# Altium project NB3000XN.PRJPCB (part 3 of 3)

## Sheet LED_RGB_SMDx8.SCHDOC: Visual Indicators
size A4; DocumentNumber: 10; SheetNumber: 11; SheetTotal: 78
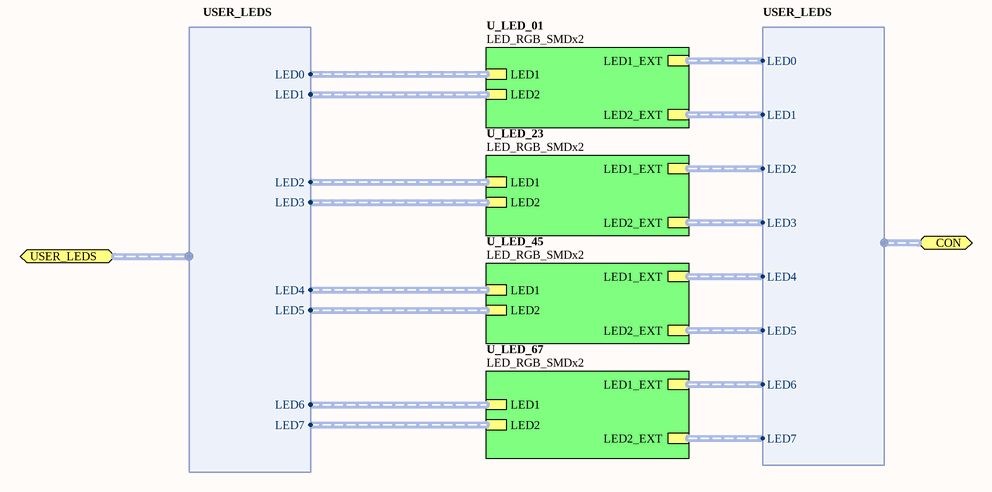
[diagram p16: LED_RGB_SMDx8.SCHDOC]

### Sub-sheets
U_LED_01 = LED_RGB_SMDx2 (file not in this document): LED1 (harness RGB_LED), LED2 (harness RGB_LED), LED1_EXT (harness RGB_LED), LED2_EXT (harness RGB_LED)
U_LED_23 = LED_RGB_SMDx2 (file not in this document): LED1 (harness RGB_LED), LED2 (harness RGB_LED), LED1_EXT (harness RGB_LED), LED2_EXT (harness RGB_LED)
U_LED_45 = LED_RGB_SMDx2 (file not in this document): LED1 (harness RGB_LED), LED2 (harness RGB_LED), LED1_EXT (harness RGB_LED), LED2_EXT (harness RGB_LED)
U_LED_67 = LED_RGB_SMDx2 (file not in this document): LED1 (harness RGB_LED), LED2 (harness RGB_LED), LED1_EXT (harness RGB_LED), LED2_EXT (harness RGB_LED)

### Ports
CON (harness USER_LEDS), USER_LEDS (harness USER_LEDS)

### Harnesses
USER_LEDS: LED0, LED1, LED2, LED3, LED4, LED5, LED6, LED7

## Sheet Audio_Codec.SchDoc: Audio CODEC
size A4; DocumentNumber: 4; SheetNumber: 6; SheetTotal: 78
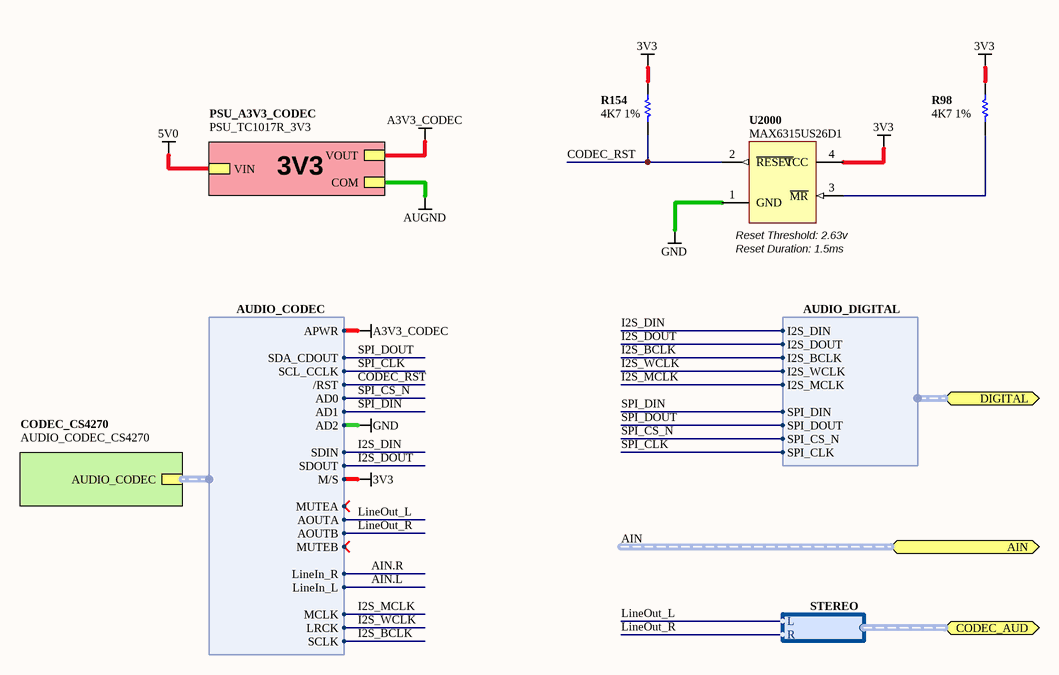
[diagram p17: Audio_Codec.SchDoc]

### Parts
(Parts that share a designator on the sheet are numbered #1, #2 ... from top to bottom, then left to right.)
R98  4K7 1%  [RESC1005-STAR]
R154#2  4K7 1%  [RESC1005-STAR]
U2000  MAX6315US26D1  [SOT143]

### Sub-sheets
CODEC_CS4270 = AUDIO_CODEC_CS4270 (file not in this document): AUDIO_CODEC (harness AUDIO_CODEC)
PSU_A3V3_CODEC = PSU_TC1017R_3V3 (file not in this document): VIN, VOUT, COM

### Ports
AIN (harness AUDIO_IN), CODEC_AUD (harness STEREO), DIGITAL (harness AUDIO_DIGITAL)

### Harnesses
AUDIO_CODEC: SDOUT, SDIN, SCLK, LRCK, MCLK, M/S, LineIn_L, LineIn_R, AOUTA, AOUTB, APWR, SCL_CCLK, AD1, SDA_CDOUT, AD0, AD2, /RST, MUTEA, MUTEB
AUDIO_DIGITAL: I2S_DOUT, I2S_DIN, I2S_BCLK, I2S_WCLK, I2S_MCLK, SPI_CLK, SPI_DIN, SPI_DOUT, SPI_CS_N
STEREO: L, R

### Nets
3V3: R98.2 R154#2.2 U2000.4(VCC) ; sheet CODEC_CS4270/AUDIO_CODEC.M/S
A3V3_CODEC: sheet PSU_A3V3_CODEC/VOUT, sheet CODEC_CS4270/AUDIO_CODEC.APWR
GND: U2000.1(GND) ; sheet CODEC_CS4270/AUDIO_CODEC.AD2
CODEC_RST: R154#2.1 U2000.2(~{RESET}) ; sheet CODEC_CS4270/AUDIO_CODEC./RST
I2S_BCLK: sheet CODEC_CS4270/AUDIO_CODEC.SCLK, port DIGITAL.I2S_BCLK  [project net CODEC.I2S_BCLK]
I2S_DIN: sheet CODEC_CS4270/AUDIO_CODEC.SDIN, port DIGITAL.I2S_DIN  [project net CODEC.I2S_DIN]
I2S_DOUT: sheet CODEC_CS4270/AUDIO_CODEC.SDOUT, port DIGITAL.I2S_DOUT  [project net CODEC.I2S_DOUT]
I2S_MCLK: sheet CODEC_CS4270/AUDIO_CODEC.MCLK, port DIGITAL.I2S_MCLK  [project net CODEC.I2S_MCLK]
I2S_WCLK: sheet CODEC_CS4270/AUDIO_CODEC.LRCK, port DIGITAL.I2S_WCLK  [project net CODEC.I2S_WCLK]
LineOut_L: sheet CODEC_CS4270/AUDIO_CODEC.AOUTA, port CODEC_AUD.L
LineOut_R: sheet CODEC_CS4270/AUDIO_CODEC.AOUTB, port CODEC_AUD.R
SPI_CLK: sheet CODEC_CS4270/AUDIO_CODEC.SCL_CCLK, port DIGITAL.SPI_CLK  [project net CODEC.SPI_CLK]
SPI_CS_N: sheet CODEC_CS4270/AUDIO_CODEC.AD0, port DIGITAL.SPI_CS_N  [project net CODEC.SPI_CS_N]
SPI_DIN: sheet CODEC_CS4270/AUDIO_CODEC.AD1, port DIGITAL.SPI_DIN  [project net CODEC.SPI_DIN]
SPI_DOUT: sheet CODEC_CS4270/AUDIO_CODEC.SDA_CDOUT, port DIGITAL.SPI_DOUT  [project net CODEC.SPI_DOUT]
NetR98_1: R98.1 U2000.3(~{MR})

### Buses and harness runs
harness AIN = port AIN

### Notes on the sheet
- 3V3
- (near U2000) Reset Threshold: 2.63v
- (near U2000) Reset Duration: 1.5ms

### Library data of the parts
R98 R154#2 = D-100-0088: Resistor, 4K7 1% 0402 (1005); Power Rating: 63 mW; Resistance: 4.7 K
U2000 = D-243-0000: MAX6315, Open-Drain Output SOT Reset IC, Customized Reset Thresholds, Timeout Delays

## Sheet CON_FFC40_LCDTFT.SCHDOC: LCD Module Connector
size A4; DocumentNumber: 63; Revision: 01; SheetNumber: 64; SheetTotal: 78
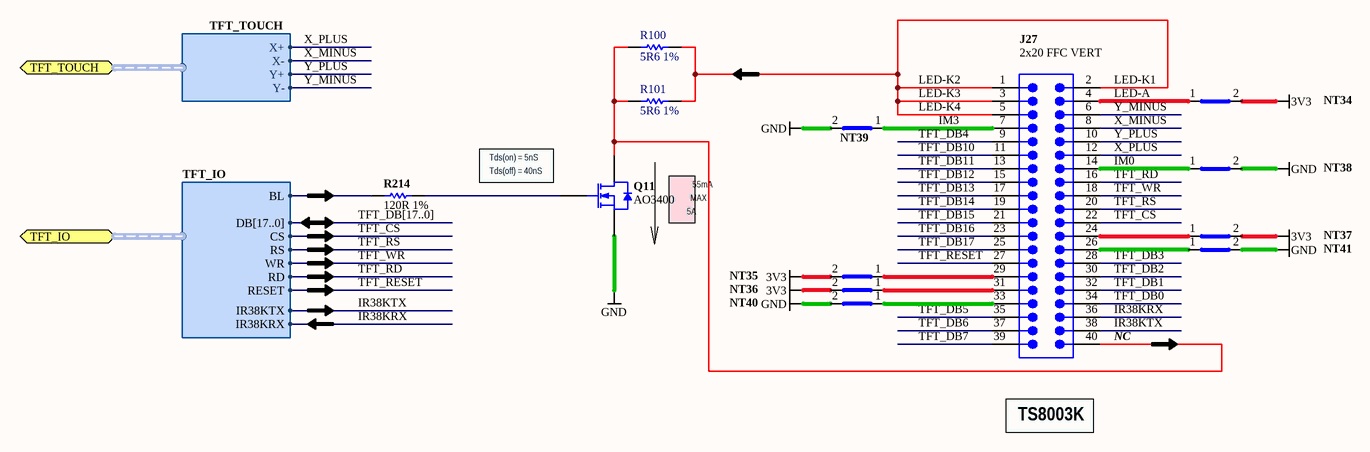
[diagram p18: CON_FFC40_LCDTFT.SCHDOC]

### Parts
J27  2x20 FFC VERT  [FPC-xxS1VN3R]
NT34  Net Tie SMT2  [NETTIE-SMT2-8X8]  (value not drawn)  (net tie, no BOM)
NT35  Net Tie SMT2  [NETTIE-SMT2-8X8]  (value not drawn)  (net tie, no BOM)
NT36  Net Tie SMT2  [NETTIE-SMT2-8X8]  (value not drawn)  (net tie, no BOM)
NT37  Net Tie SMT2  [NETTIE-SMT2-8X8]  (value not drawn)  (net tie, no BOM)
NT38  Net Tie SMT2  [NETTIE-SMT2-8X8]  (value not drawn)  (net tie, no BOM)
NT39  Net Tie SMT2  [NETTIE-SMT2-8X8]  (value not drawn)  (net tie, no BOM)
NT40  Net Tie SMT2  [NETTIE-SMT2-8X8]  (value not drawn)  (net tie, no BOM)
NT41  Net Tie SMT2  [NETTIE-SMT2-8X8]  (value not drawn)  (net tie, no BOM)
Q11  AO3400  [SOT95P230-3D]
R100  5R6 1%  [RESC1005-STAR]
R101  5R6 1%  [RESC1005-STAR]
R214  120R 1%  [RESC1005-STAR]

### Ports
TFT_IO (harness TFT_IO), TFT_TOUCH (harness TFT_TOUCH)

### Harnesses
TFT_IO: CS, RS, WR, RD, RESET, DB[17..0], BL, IR38KTX, IR38KRX
TFT_TOUCH: X+, X-, Y+, Y-

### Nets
3V3: NT34.2(Net2) NT35.2(Net2) NT36.2(Net2) NT37.2(Net2)
GND: NT38.2(Net2) NT39.2(Net2) NT40.2(Net2) NT41.2(Net2) Q11.3(S)
IR38KRX: J27.36 ; port TFT_IO.IR38KRX  [project net TFT_IO.IR38KRX]
IR38KTX: J27.38 ; port TFT_IO.IR38KTX  [project net TFT_IO.IR38KTX]
TFT_CS: J27.22 ; port TFT_IO.CS  [project net TFT_IO.CS]
TFT_DB0: J27.34
TFT_DB1: J27.32
TFT_DB2: J27.30
TFT_DB3: J27.28
TFT_DB4: J27.9
TFT_DB5: J27.35
TFT_DB6: J27.37
TFT_DB7: J27.39
TFT_DB10: J27.11
TFT_DB11: J27.13
TFT_DB12: J27.15
TFT_DB13: J27.17
TFT_DB14: J27.19
TFT_DB15: J27.21
TFT_DB16: J27.23
TFT_DB17: J27.25
TFT_IO.BL: R214.2 ; port TFT_IO.BL
TFT_RD: J27.16 ; port TFT_IO.RD  [project net TFT_IO.RD]
TFT_RESET: J27.27 ; port TFT_IO.RESET  [project net TFT_IO.RESET]
TFT_RS: J27.20 ; port TFT_IO.RS  [project net TFT_IO.RS]
TFT_WR: J27.18 ; port TFT_IO.WR  [project net TFT_IO.WR]
X_MINUS: J27.8 ; port TFT_TOUCH.X-  [project net TFT_TOUCH.X-]
X_PLUS: J27.12 ; port TFT_TOUCH.X+  [project net TFT_TOUCH.X+]
Y_MINUS: J27.6 ; port TFT_TOUCH.Y-  [project net TFT_TOUCH.Y-]
Y_PLUS: J27.10 ; port TFT_TOUCH.Y+  [project net TFT_TOUCH.Y+]
NetJ27_1: J27.1 J27.2 J27.3 J27.5 R100.1 R101.1
NetJ27_4: J27.4 NT34.1(Net1)
NetJ27_7: J27.7 NT39.1(Net1)
NetJ27_14: J27.14 NT38.1(Net1)
NetJ27_24: J27.24 NT37.1(Net1)
NetJ27_26: J27.26 NT41.1(Net1)
NetJ27_29: J27.29 NT35.1(Net1)
NetJ27_31: J27.31 NT36.1(Net1)
NetJ27_33: J27.33 NT40.1(Net1)
NetJ27_40: J27.40 Q11.2(D) R100.2 R101.2
NetQ11_1: Q11.1(G) R214.1

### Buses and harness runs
bus TFT_DB[17..0]

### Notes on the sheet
- LED-K3
- LED-K2
- LED-K4
- (near NT39) IM3
- LED-K1
- LED-A
- (near Q11) Tds(on) = 5nS
- (near Q11) Tds(off) = 40nS
- 55mA
- (near J27) IM0
- 5A
- MAX
- (near J27) NC
- TS8003K

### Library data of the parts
J27 = D-300-0125: Header FFC, 2x20 pin Vertical, 0.5mm; Connector type: Straight; Max Current: mA
NT34-NT41 = D-002-0003: Net-Tie, Surface Mount, 2 x 1.6mm x 0.8mm SMT Pads - For 0.8mm Track
Q11 = D-158-0005: N-channel Enhancement Mode Field-effect Transistor;  5.8A/30V; Transistor Type: NPN
R100 R101 = D-100-0085: Resistor, 5R6 1% 0402 (1005); Power Rating: 63mW; Resistance: 5.6R
R214 = D-100-0126: Resistor, 120R 1% 0402 (1005); Power Rating: 63 mW

## Sheet Mounts.SchDoc: NB3000XN Holes and Graphics
size A4; Organization: Altium Limited.; Address1: 3 Minna Close; Address2: Belrose; Address3: NSW 2085; Address4: AUSTRALIA; DocumentNumber: 19; Revision: 6; SheetNumber: 20; SheetTotal: 78
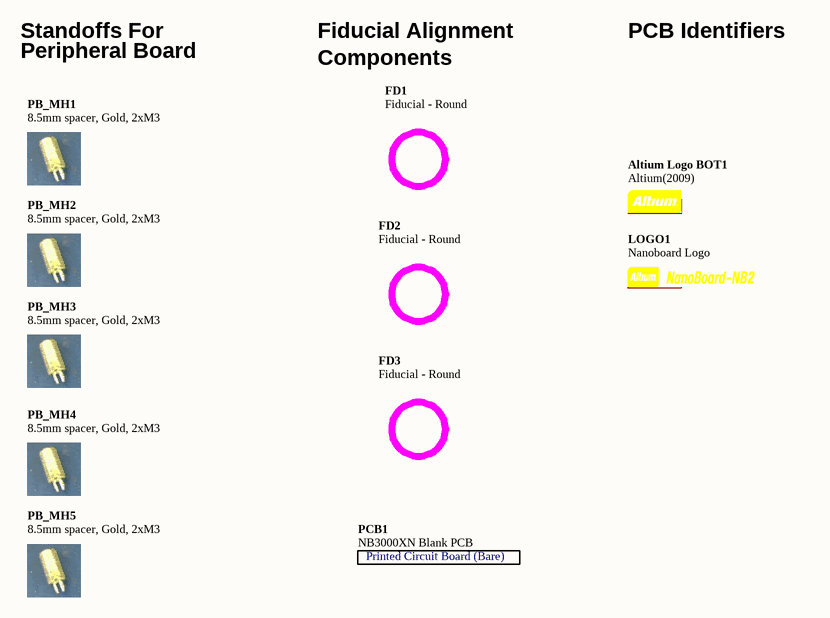
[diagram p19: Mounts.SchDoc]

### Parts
Altium_Logo_BOT1  Altium(2009)  [Logo-Altium-New]  (no BOM)
FD1  Fiducial - Round  [FIDUCIAL ROUND]  (no BOM)
FD2  Fiducial - Round  [FIDUCIAL ROUND]  (no BOM)
FD3  Fiducial - Round  [FIDUCIAL ROUND]  (no BOM)
LOGO1  Nanoboard Logo  [NANOBOARD LOGO]  (no BOM)
PB_MH1  8.5mm spacer, Gold, 2xM3  [STANDOFF_SOLDER_3MM]
PB_MH2  8.5mm spacer, Gold, 2xM3  [STANDOFF_SOLDER_3MM]
PB_MH3  8.5mm spacer, Gold, 2xM3  [STANDOFF_SOLDER_3MM]
PB_MH4  8.5mm spacer, Gold, 2xM3  [STANDOFF_SOLDER_3MM]
PB_MH5  8.5mm spacer, Gold, 2xM3  [STANDOFF_SOLDER_3MM]
PCB1  NB3000XN Blank PCB  [NB2STR01 Blank PCB]

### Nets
SHIELD: PB_MH1.STAND PB_MH2.STAND PB_MH3.STAND PB_MH4.STAND PB_MH5.STAND

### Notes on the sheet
- Peripheral Board
- Standoffs For
- Fiducial Alignment
- Components
- PCB Identifiers

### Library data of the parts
Altium_Logo_BOT1 = D-000-0003: Altium Logo for PCB
FD1-FD3 = D-004-0001: Fiducial - Round 1.5mm Top-Bottom
LOGO1 = D-000-0000
PB_MH1-PB_MH5 = D-306-0001: Spacer, 8.5mm GOLD, Splitted bottom, Female M3-thread
PCB1 = D-810-0050: NB3000XN Blank PCB - NanoBoard  3000 Series with Xilinx-3AN; ProjectPath: NB2STR01.PrjPCB

## Sheet PWJACK+SWITCH.SchDoc: Power Jack & Switch
size A4; Organization: Altium Limited.; Address1: Level 3, 12a Rodborough Rd; Address2: Frenchs Forest 2086; Address3: NSW; Address4: AUSTRALIA; DocumentNumber: 20; Revision: 6; SheetNumber: 21; SheetTotal: 78
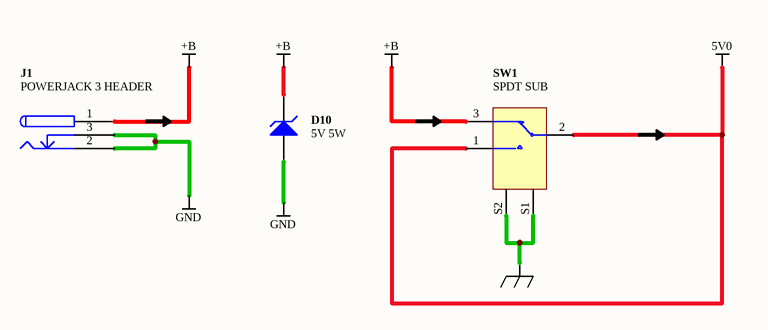
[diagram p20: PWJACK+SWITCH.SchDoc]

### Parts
(Parts that share a designator on the sheet are numbered #1, #2 ... from top to bottom, then left to right.)
D10  5V 5W  [DIOM8059]
J1#4  POWERJACK 3 HEADER  [KLD-0202]
SW1  SPDT SUB  [T8019L-TNQ]

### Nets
5V0: SW1.1 SW1.2
+B: D10.2(K) J1#4.1 SW1.3
GND: D10.1(A) J1#4.2 J1#4.3
SHIELD: SW1.S1 SW1.S2

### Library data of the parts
D10 = D-150-0001: Zener Diode, 5V 5W; Max Forward Current: mA; Rated Voltage: mV
J1#4 = D-300-0007: Connector, 3 Conductor Power Jack 2 break 2 aux contacts
SW1 = D-301-0000: Switch, SPDT Subminiature Toggle

## Sheet USERPWR.SchDoc: USER HEADER POWER
size A4; Organization: Altium Limited.; Address1: Level 3, 12a Rodborough Rd; Address2: Frenchs Forest 2086; Address3: NSW; Address4: AUSTRALIA; DocumentNumber: 25; SheetNumber: 26; SheetTotal: 78
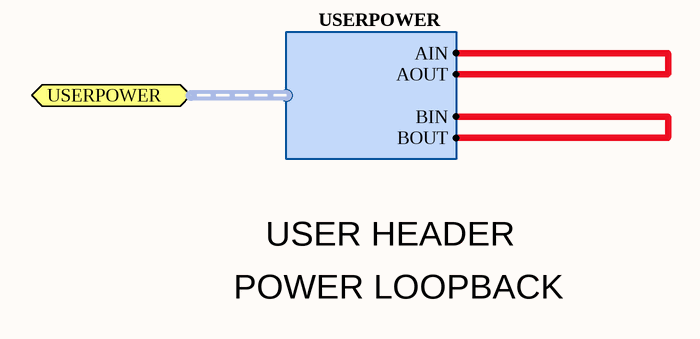
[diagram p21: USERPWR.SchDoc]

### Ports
USERPOWER (harness USERPOWER)

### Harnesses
USERPOWER: AIN, BIN, AOUT, BOUT

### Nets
UIO_PWR.AIN: port USERPOWER.AIN, port USERPOWER.AOUT
UIO_PWR.BIN: port USERPOWER.BIN, port USERPOWER.BOUT

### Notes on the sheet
- POWER LOOPBACK
- USER HEADER

## Sheet CON_AUDIO_AC99_NOMIC.SchDoc: AUDIO AC99 Interface
size A4; Organization: Altium Limited.; Address1: Level 3, 12a Rodborough Rd; Address2: Frenchs Forest 2086; Address3: NSW; Address4: AUSTRALIA; DocumentNumber: 59; SheetNumber: 60; SheetTotal: 78
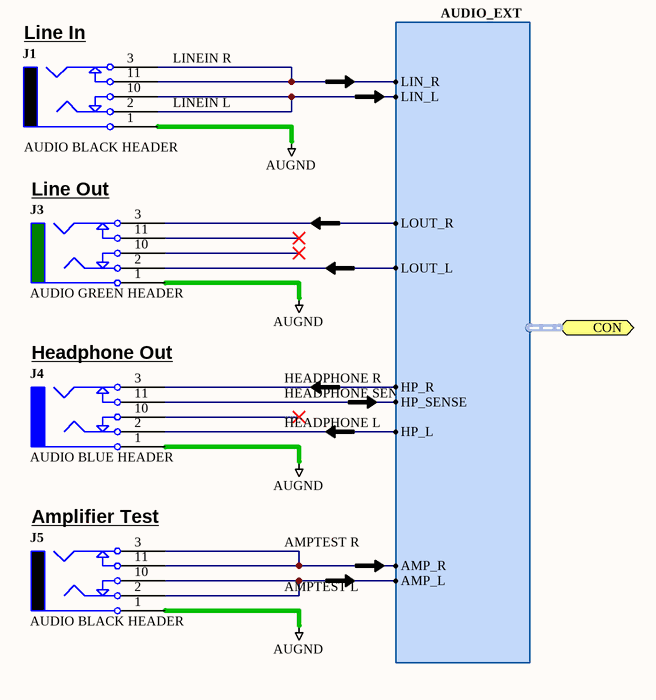
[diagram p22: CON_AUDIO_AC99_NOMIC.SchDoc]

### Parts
(Parts that share a designator on the sheet are numbered #1, #2 ... from top to bottom, then left to right.)
J1#5  AUDIO BLACK HEADER  [TSH-3675]
J3#2  AUDIO GREEN HEADER  [TSH-3675]
J4  AUDIO BLUE HEADER  [TSH-3675]
J5  AUDIO BLACK HEADER  [TSH-3675]

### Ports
CON (harness AUDIO_EXT)

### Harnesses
AUDIO_EXT: AMP_L, AMP_R, HP_L, HP_R, HP_SENSE, LIN_L, LIN_R, LOUT_L, LOUT_R

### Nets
AUGND: J1#5.1 J3#2.1 J4.1 J5.1
AUDIO.AMP_L: J5.2 J5.10 ; port CON.AMP_L
AUDIO.AMP_R: J5.3 J5.11 ; port CON.AMP_R
AUDIO.HP_L: J4.2 ; port CON.HP_L
AUDIO.HP_R: J4.3 ; port CON.HP_R
AUDIO.HP_SENSE: J4.11 ; port CON.HP_SENSE
AUDIO.LIN_L: J1#5.2 J1#5.10 ; port CON.LIN_L
AUDIO.LIN_R: J1#5.3 J1#5.11 ; port CON.LIN_R
AUDIO.LOUT_L: J3#2.2 ; port CON.LOUT_L
AUDIO.LOUT_R: J3#2.3 ; port CON.LOUT_R

Not connected (* = marked no-connect by the designer): J3#2 10* 11*; J4 10*

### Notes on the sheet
- (near J1#5) Line In
- LINEIN R
- LINEIN L
- (near J3#2) Line Out
- (near J4) Headphone Out
- HEADPHONE R
- HEADPHONE L
- HEADPHONE SENSE
- (near J5) Amplifier Test
- AMPTEST R
- AMPTEST L

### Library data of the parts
J1#5 J5 = D-300-0033: Connector, 3.5mm Stereo Audio Socket, Black, 2 break contacts (normals) and 2 auxiliary make contacts
J3#2 = D-300-0031: Connector, 3.5mm Stereo Audio Socket, Green, 2 break contacts (normals) and 2 auxiliary make contacts
J4 = D-300-0032: Connector, 3.5mm Stereo Audio Socket, Blue, 2 break contacts (normals) and 2 auxiliary make contacts

## Sheet OSC_24MHZ.SchDoc: 24MHz Oscillator
size A4; Organization: Altium Limited.; Address1: Level 3, 12a Rodborough Rd; Address2: Frenchs Forest 2086; Address3: NSW; Address4: AUSTRALIA; DocumentNumber: 50; SheetNumber: 51; SheetTotal: 78
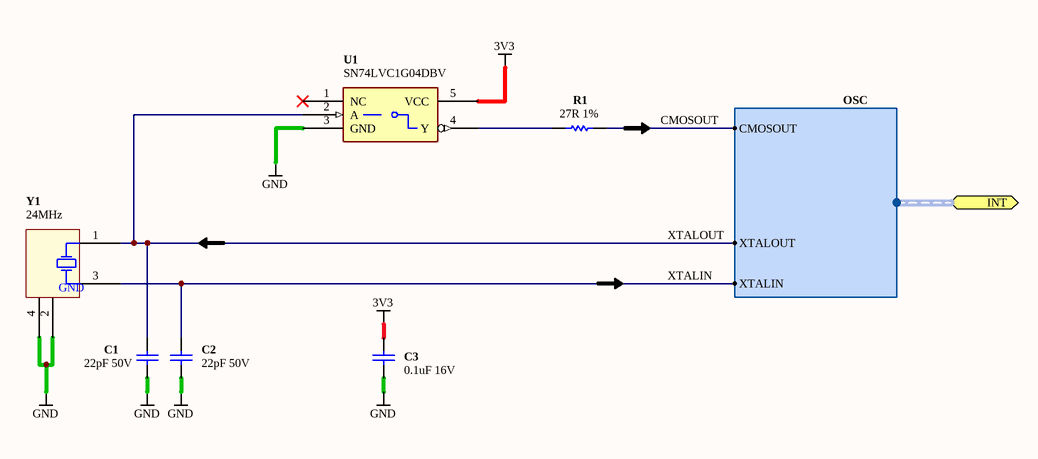
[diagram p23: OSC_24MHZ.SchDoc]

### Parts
(Parts that share a designator on the sheet are numbered #1, #2 ... from top to bottom, then left to right.)
C1#4  22pF 50V  [CAPC1005-STAR]
C2#4  22pF 50V  [CAPC1005-STAR]
C3#4  0.1uF 16V  [CAPC1005-STAR]
R1#6  27R 1%  [RESC1005-STAR]
U1#7  SN74LVC1G04DBV  [SOT95P280-5]
Y1#2  24MHz  [XTAL-200X126-4]

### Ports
INT (harness OSC)

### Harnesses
OSC: CMOSOUT, XTALIN, XTALOUT

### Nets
3V3: C3#4.1 U1#7.5(VCC)
GND: C1#4.2 C2#4.2 C3#4.2 U1#7.3(GND) Y1#2.2(GND) Y1#2.4(GND)
CMOSOUT: R1#6.1 ; port INT.CMOSOUT  [project net DBUSB.XTALIN]
XTALIN: C2#4.1 Y1#2.3(X2) ; port INT.XTALIN  [project net HOST_USB.XTALIN]
XTALOUT: C1#4.1 U1#7.2(A) Y1#2.1(X1) ; port INT.XTALOUT  [project net HOST_USB.XTALOUT]
NetR1#6_2: R1#6.2 U1#7.4(Y)

Not connected (* = marked no-connect by the designer): U1#7 1(NC)*

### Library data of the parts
C1#4 C2#4 = D-101-0059: Capacitor, Ceramic, 22pF 5% 50V 0402 (1005) COG; Polarity: Non-Polarized
C3#4 = D-101-0080: Capacitor, Ceramic, 0.1uF 10% 16V 0402 (1005) X7R; Polarity: Non-Polarized
R1#6 = D-100-0108: Resistor, 27R 1% 0402 (1005); Power Rating: 63 mW
U1#7 = D-205-0001: SN74LVC1G04DBV, Single Inverter Gate, 1.65-V to 5.5-V
Y1#2 = D-103-0013: Crystal, SMD, 24.000000MHz Stab=30ppm 20.0pF; Frequency Stability: 30 ppm; Load Capacitance: 20 pF; Nominal Operational Voltage: mV

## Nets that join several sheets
1V2: PSU (TP7.1), FPGA_NonIO (23 pins), FPGA_USER/USER_DECOUPLING_CAPS_1V2 (12 pins), HOST_FPGA_NonIO (9 pins), FPGA_HOST/HOST_DECOUPLING_CAPS_1V2 (12 pins)
3V3: PSU (TP4.1), FPGA (10 pins), FPGA_NonIO (50 pins), FPGA_USER/USER_DECOUPLING_CAPS_3V3 (48 pins), VIDEO_DAC_THS8134B (C1#2.1 U1#3.12 U1#3.23 U1#3.24), Host_FPGA (6 pins), HOST_FPGA_NonIO (36 pins), FPGA_HOST/HOST_DECOUPLING_CAPS_3V3 (48 pins), DBUSB_TXRX (19 pins), Ethernet_RTL8201CL (19 pins), TSC_XPT2046 (R2#6.1), Audio_Codec (R98.2 R154#2.2 U2000.4), CON_FFC40_LCDTFT (NT34.2 NT35.2 NT36.2 NT37.2), DBUSB_TXRX (19 pins), OSC_24MHZ (C3#4.1 U1#7.5)
5V0: PSU (6 pins), VIDEO_DAC_THS8134B (L1#1.1), TSC_XPT2046 (NT9.2), PWJACK+SWITCH (SW1.1 SW1.2)
+B: PSU (TP3.1), PWJACK+SWITCH (D10.2 J1#4.1 SW1.3)
AUGND: PSU (NT1#1.1), CON_AUDIO_AC99_NOMIC (J1#5.1 J3#2.1 J4.1 J5.1)
GND: PSU (16 pins), FPGA (5 pins), FPGA_NonIO (78 pins), FPGA_USER/USER_DECOUPLING_CAPS_1V2 (12 pins), FPGA_USER/USER_DECOUPLING_CAPS_3V3 (48 pins), VGA_OUT (U1#2.2), VIDEO_DAC_THS8134B (17 pins), Host_FPGA (J1#2.2 R3#3.2), HOST_FPGA_NonIO (44 pins), FPGA_HOST/HOST_DECOUPLING_CAPS_1V2 (12 pins), FPGA_HOST/HOST_DECOUPLING_CAPS_3V3 (48 pins), HOST_JTAG (J1#3.9 J1#3.10), DBUSB_TXRX (21 pins), Ethernet_RTL8201CL (50 pins), TSC_XPT2046 (NT11#2.1 U1#6.6 U1#6.7 U1#6.8), Audio_Codec (U2000.1), CON_FFC40_LCDTFT (5 pins), PWJACK+SWITCH (D10.1 J1#4.2 J1#4.3), DBUSB_TXRX (21 pins), OSC_24MHZ (6 pins)
SHIELD: PSU (C169.1 R248.1), Mounts (5 pins), PWJACK+SWITCH (SW1.S1 SW1.S2)
DB_CLOCKS.FPGA_CLK: FPGA (U1#1.AE13), Host_FPGA (U1#4.C10)
DB_CLOCKS.FPGA_CLK1: FPGA (U1#1.Y14), Host_FPGA (R1_HOST.2)
DB_CLOCKS.REF_CLK: FPGA (U1#1.K14), Host_FPGA (U1#4.A10)
DB_PROGRAM.CCLK: FPGA (R20#1.1), Host_FPGA (U1#4.V10)
DB_PROGRAM.DIN: FPGA (U1#1.AF24), Host_FPGA (U1#4.T1)
DB_PROGRAM.DONE: FPGA (R4#1.1 R22#1.1), Host_FPGA (U1#4.R2)
DB_PROGRAM.INIT: FPGA (R3#1.1 U1#1.AA15), Host_FPGA (U1#4.U3)
DB_PROGRAM.PROGRAM: FPGA (R1#1.1 R24#1.1), Host_FPGA (U1#4.R7)
DB_SPI.CLK: FPGA (U1#1.AE14), Host_FPGA (U1#4.W1)
DB_SPI.DIN: FPGA (U1#1.Y26), Host_FPGA (U1#4.N1)
DB_SPI.DOUT: FPGA (U1#1.AD21), Host_FPGA (U1#4.U1)
DB_SPI.MODE: FPGA (U1#1.AF25), Host_FPGA (U1#4.J1)
DB_SPI.SEL: FPGA (U1#1.AE23), Host_FPGA (U1#4.R3)
DBUSB.FIFOADR0: FPGA (U1#1.AA17), DBUSB_TXRX (U3A.37)
DBUSB.FIFOADR1: FPGA (U1#1.AD25), DBUSB_TXRX (U3A.38)
DBUSB.FIFOADR2: FPGA (U1#1.AA18), DBUSB_TXRX (U3A.36)
DBUSB.FLAGA: FPGA (U1#1.AC17), DBUSB_TXRX (U3A.29)
DBUSB.FLAGB: FPGA (U1#1.AB17), DBUSB_TXRX (U3A.30)
DBUSB.FLAGC: FPGA (U1#1.AA20), DBUSB_TXRX (U3A.31)
DBUSB.FLAGD_CS_N: FPGA (U1#1.AE20), DBUSB_TXRX (U3A.40)
DBUSB.IFCLK: FPGA (U1#1.V14), DBUSB_TXRX (R6A.1)
DBUSB.INT_N: FPGA (U1#1.AF22), DBUSB_TXRX (R7A.1 U3A.34)
DBUSB.PKTEND: FPGA (U1#1.AE21), DBUSB_TXRX (U3A.39)
DBUSB.RD_N: FPGA (U1#1.U16), DBUSB_TXRX (U3A.1)
DBUSB.READY: FPGA (U1#1.R24), DBUSB_TXRX (U3A.33)
DBUSB.RESET_N: FPGA (U1#1.V17), DBUSB_TXRX (U1000A.3)
DBUSB.SLOE: FPGA (U1#1.AB18), DBUSB_TXRX (U3A.35)
DBUSB.VBUS: FPGA (U1#1.AC18), DBUSB_TXRX (R2A.1 R3A.1)
DBUSB.WR_N: FPGA (U1#1.U18), DBUSB_TXRX (U3A.2)
DONE: FPGA (R22#1.2), FPGA_NonIO (U1#1.AB21)
E_RXD0: FPGA (U1#1.C1), Ethernet_RTL8201CL (U1#5.21)
E_RXD1: FPGA (U1#1.D2), Ethernet_RTL8201CL (U1#5.20)
E_RXD2: FPGA (U1#1.D1), Ethernet_RTL8201CL (U1#5.19)
E_RXD3: FPGA (U1#1.G5), Ethernet_RTL8201CL (U1#5.18)
E_TXD0: FPGA (U1#1.F4), Ethernet_RTL8201CL (R5#2.1 U1#5.6)
E_TXD1: FPGA (U1#1.E1), Ethernet_RTL8201CL (R4#3.1 U1#5.5)
E_TXD2: FPGA (U1#1.G6), Ethernet_RTL8201CL (R3#5.1 U1#5.4)
E_TXD3: FPGA (U1#1.F5), Ethernet_RTL8201CL (R2#5.1 U1#5.3)
ETH.E_COL: FPGA (U1#1.G1), Ethernet_RTL8201CL (R10#2.1 U1#5.1)
ETH.E_CRS: FPGA (U1#1.A5), Ethernet_RTL8201CL (U2.12)
ETH.E_MDC: FPGA (U1#1.B2), Ethernet_RTL8201CL (R7#2.1 U1#5.25)
ETH.E_MDIO: FPGA (U1#1.D3), Ethernet_RTL8201CL (R6#2.1 U1#5.26)
ETH.E_RESETB_E: FPGA (U1#1.E4), Ethernet_RTL8201CL (R19.1 U1#5.42)
ETH.E_RXC: FPGA (U1#1.B14), Ethernet_RTL8201CL (U1#5.16)
ETH.E_RXDV: FPGA (U1#1.C2), Ethernet_RTL8201CL (U1#5.22)
ETH.E_RXER: FPGA (U1#1.A7), Ethernet_RTL8201CL (U2.14)
ETH.E_TXC: FPGA (U1#1.H4), Ethernet_RTL8201CL (U1#5.7)
ETH.E_TXEN: FPGA (U1#1.F3), Ethernet_RTL8201CL (R1#5.1 U1#5.2)
FPGA_ID0: FPGA (NT2#2.1), Host_FPGA (U1#4.E20)
FPGA_ID1: FPGA (NT3#3.1), Host_FPGA (U1#4.R4)
FPGA_ID2: FPGA (NT4.1), Host_FPGA (U1#4.F20)
FPGA_ID3: FPGA (NT5.1), Host_FPGA (U1#4.R1)
FPGA_M0: FPGA (R23#1.1), Host_FPGA (U1#4.R5)
FPGA_M1: FPGA (R18#1.1), Host_FPGA (U1#4.V2)
FPGA_M2: FPGA (R14#1.1), Host_FPGA (U1#4.U5)
FPGA_TCK: FPGA (R9#1.1), Host_FPGA (U1#4.E10)
FPGA_TDI: FPGA (R12#1.1), Host_FPGA (U1#4.T6)
FPGA_TDO: FPGA (R2#1.1 R10#1.1), Host_FPGA (U1#4.W2)
FPGA_TMS: FPGA (R8#1.1), Host_FPGA (U1#4.V1)
HOST_HARD_TCK: HOST_FPGA_NonIO (R156.1), HOST_JTAG (J1#3.3)
HOST_HARD_TDI: HOST_FPGA_NonIO (R154#1.1), HOST_JTAG (J1#3.1)
HOST_HARD_TDO: HOST_FPGA_NonIO (R155.1), HOST_JTAG (J1#3.2)
HOST_HARD_TMS: HOST_FPGA_NonIO (R157.1), HOST_JTAG (J1#3.4)
HOST_SOFT_TCK: Host_FPGA (U1#4.D10), HOST_JTAG (J1#3.7)
HOST_SOFT_TDI: Host_FPGA (U1#4.F3), HOST_JTAG (J1#3.5)
HOST_SOFT_TDO: Host_FPGA (U1#4.F2), HOST_JTAG (J1#3.6)
HOST_SOFT_TMS: Host_FPGA (U1#4.F7), HOST_JTAG (J1#3.8)
HOST_USB.FIFOADR0: Host_FPGA (U1#4.L1), DBUSB_TXRX (U3B.37)
HOST_USB.FIFOADR1: Host_FPGA (U1#4.L3), DBUSB_TXRX (U3B.38)
HOST_USB.FIFOADR2: Host_FPGA (U1#4.K3), DBUSB_TXRX (U3B.36)
HOST_USB.FLAGA: Host_FPGA (U1#4.G1), DBUSB_TXRX (U3B.29)
HOST_USB.FLAGB: Host_FPGA (U1#4.J3), DBUSB_TXRX (U3B.30)
HOST_USB.FLAGC: Host_FPGA (U1#4.J4), DBUSB_TXRX (U3B.31)
HOST_USB.FLAGD_CS_N: Host_FPGA (U1#4.M1), DBUSB_TXRX (U3B.40)
HOST_USB.IFCLK: Host_FPGA (U1#4.H2), DBUSB_TXRX (R6B.1)
HOST_USB.INT_N: Host_FPGA (U1#4.J6), DBUSB_TXRX (R7B.1 U3B.34)
HOST_USB.PKTEND: Host_FPGA (U1#4.L5), DBUSB_TXRX (U3B.39)
HOST_USB.RD_N: Host_FPGA (U1#4.N2), DBUSB_TXRX (U3B.1)
HOST_USB.READY: Host_FPGA (U1#4.J5), DBUSB_TXRX (U3B.33)
HOST_USB.RESET_N: Host_FPGA (U1#4.P4), DBUSB_TXRX (U1000B.3)
HOST_USB.SLOE: Host_FPGA (U1#4.K2), DBUSB_TXRX (U3B.35)
HOST_USB.VBUS: Host_FPGA (U1#4.F1), DBUSB_TXRX (R2B.1 R3B.1)
HOST_USB.WR_N: Host_FPGA (U1#4.K4), DBUSB_TXRX (U3B.2)
HUSB_D0: FPGA (U1#1.AE17), DBUSB_TXRX (U3A.18)
HUSB_D0: Host_FPGA (U1#4.H4), DBUSB_TXRX (U3B.18)
HUSB_D1: FPGA (U1#1.U15), DBUSB_TXRX (U3A.19)
HUSB_D1: Host_FPGA (U1#4.F6), DBUSB_TXRX (U3B.19)
HUSB_D2: FPGA (U1#1.AD17), DBUSB_TXRX (U3A.20)
HUSB_D2: Host_FPGA (U1#4.H6), DBUSB_TXRX (U3B.20)
HUSB_D3: FPGA (U1#1.Y15), DBUSB_TXRX (U3A.21)
HUSB_D3: Host_FPGA (U1#4.G3), DBUSB_TXRX (U3B.21)
HUSB_D4: FPGA (U1#1.AC24), DBUSB_TXRX (U3A.22)
HUSB_D4: Host_FPGA (U1#4.G5), DBUSB_TXRX (U3B.22)
HUSB_D5: FPGA (U1#1.AF19), DBUSB_TXRX (U3A.23)
HUSB_D5: Host_FPGA (U1#4.G4), DBUSB_TXRX (U3B.23)
HUSB_D6: FPGA (U1#1.AE19), DBUSB_TXRX (U3A.24)
HUSB_D6: Host_FPGA (U1#4.J2), DBUSB_TXRX (U3B.24)
HUSB_D7: FPGA (U1#1.AF20), DBUSB_TXRX (U3A.25)
HUSB_D7: Host_FPGA (U1#4.H3), DBUSB_TXRX (U3B.25)
HUSB_D8: Host_FPGA (U1#4.P3), DBUSB_TXRX (U3B.45)
HUSB_D9: Host_FPGA (U1#4.M5), DBUSB_TXRX (U3B.46)
HUSB_D10: Host_FPGA (U1#4.P1), DBUSB_TXRX (U3B.47)
HUSB_D11: Host_FPGA (U1#4.M4), DBUSB_TXRX (U3B.48)
HUSB_D12: Host_FPGA (U1#4.N4), DBUSB_TXRX (U3B.49)
HUSB_D13: Host_FPGA (U1#4.M3), DBUSB_TXRX (U3B.50)
HUSB_D14: Host_FPGA (U1#4.N3), DBUSB_TXRX (U3B.51)
HUSB_D15: Host_FPGA (U1#4.M2), DBUSB_TXRX (U3B.52)
NEXUS_TCK: FPGA (U1#1.AF14), Host_FPGA (U1#4.W9)
NEXUS_TDI: FPGA (U1#1.AA19), Host_FPGA (U1#4.T4)
NEXUS_TDO: FPGA (U1#1.AC20), Host_FPGA (U1#4.T3)
NEXUS_TMS: FPGA (U1#1.AB20), Host_FPGA (U1#4.T2)
PROG_B: FPGA (R24#1.2), FPGA_NonIO (U1#1.A2)
TCK: FPGA (R9#1.2), FPGA_NonIO (U1#1.A25)
TDI: FPGA (R12#1.2), FPGA_NonIO (U1#1.G7)
TDO: FPGA (R10#1.2), FPGA_NonIO (U1#1.E23)
TFT_DB0: FPGA (U1#1.AD14), CON_FFC40_LCDTFT (J27.34)
TFT_DB1: FPGA (U1#1.AB15), CON_FFC40_LCDTFT (J27.32)
TFT_DB2: FPGA (U1#1.AE12), CON_FFC40_LCDTFT (J27.30)
TFT_DB3: FPGA (U1#1.AE15), CON_FFC40_LCDTFT (J27.28)
TFT_DB4: FPGA (U1#1.AF23), CON_FFC40_LCDTFT (J27.9)
TFT_DB5: FPGA (U1#1.AC15), CON_FFC40_LCDTFT (J27.35)
TFT_DB6: FPGA (U1#1.AC14), CON_FFC40_LCDTFT (J27.37)
TFT_DB7: FPGA (U1#1.AC12), CON_FFC40_LCDTFT (J27.39)
TFT_DB10: FPGA (U1#1.AC21), CON_FFC40_LCDTFT (J27.11)
TFT_DB11: FPGA (U1#1.AD22), CON_FFC40_LCDTFT (J27.13)
TFT_DB12: FPGA (U1#1.AC19), CON_FFC40_LCDTFT (J27.15)
TFT_DB13: FPGA (U1#1.Y17), CON_FFC40_LCDTFT (J27.17)
TFT_DB14: FPGA (U1#1.AD19), CON_FFC40_LCDTFT (J27.19)
TFT_DB15: FPGA (U1#1.W17), CON_FFC40_LCDTFT (J27.21)
TFT_DB16: FPGA (U1#1.AB16), CON_FFC40_LCDTFT (J27.23)
TFT_DB17: FPGA (U1#1.W15), CON_FFC40_LCDTFT (J27.25)
TFT_IO.BL: FPGA (U1#1.AC23), CON_FFC40_LCDTFT (R214.2)
TFT_IO.CS: FPGA (U1#1.AC16), CON_FFC40_LCDTFT (J27.22)
TFT_IO.IR38KRX: FPGA (U1#1.W13), CON_FFC40_LCDTFT (J27.36)
TFT_IO.IR38KTX: FPGA (U1#1.Y12), CON_FFC40_LCDTFT (J27.38)
TFT_IO.RD: FPGA (U1#1.AD20), CON_FFC40_LCDTFT (J27.16)
TFT_IO.RESET: FPGA (U1#1.V15), CON_FFC40_LCDTFT (J27.27)
TFT_IO.RS: FPGA (U1#1.AF18), CON_FFC40_LCDTFT (J27.20)
TFT_IO.WR: FPGA (U1#1.AE18), CON_FFC40_LCDTFT (J27.18)
TFT_TOUCH.X+: TSC_XPT2046 (U1#6.2), CON_FFC40_LCDTFT (J27.12)
TFT_TOUCH.X-: TSC_XPT2046 (U1#6.4), CON_FFC40_LCDTFT (J27.8)
TFT_TOUCH.Y+: TSC_XPT2046 (U1#6.3), CON_FFC40_LCDTFT (J27.10)
TFT_TOUCH.Y-: TSC_XPT2046 (U1#6.5), CON_FFC40_LCDTFT (J27.6)
TFT_TSC.BUSY: FPGA (U1#1.W26), TSC_XPT2046 (U1#6.13)
TFT_TSC.CLK: FPGA (U1#1.Y13), TSC_XPT2046 (U1#6.16)
TFT_TSC.CS_N: FPGA (U1#1.AB26), TSC_XPT2046 (U1#6.15)
TFT_TSC.DIN: FPGA (U1#1.AD26), TSC_XPT2046 (U1#6.14)
TFT_TSC.DOUT: FPGA (U1#1.W25), TSC_XPT2046 (U1#6.12)
TFT_TSC.TFT_INT: FPGA (U1#1.AE25), TSC_XPT2046 (R2#6.2 U1#6.11)
TMS: FPGA (R8#1.2), FPGA_NonIO (U1#1.D4)
VGA#.BLUE: VGA_OUT (U1#2.3), VIDEO_DAC_THS8134B (R2#2.1 R3#2.2 U1#3.45)
VGA#.GREEN: VGA_OUT (U1#2.4), VIDEO_DAC_THS8134B (R4#2.1 R5#1.2 U1#3.41)
VGA#.HSYNC: FPGA (U1#1.C11), VGA_OUT (U1#2.6)
VGA#.RED: VGA_OUT (U1#2.1), VIDEO_DAC_THS8134B (R6#1.2 R7#1.2 U1#3.43)
VGA#.VSYNC: FPGA (U1#1.H12), VGA_OUT (U1#2.5)
VGA.VGA_CLK: FPGA (U1#1.C5), VIDEO_DAC_THS8134B (U1#3.26)
VGA_BLUE0: FPGA (U1#1.K12), VIDEO_DAC_THS8134B (U1#3.8)
VGA_BLUE1: FPGA (U1#1.D11), VIDEO_DAC_THS8134B (U1#3.7)
VGA_BLUE2: FPGA (U1#1.J11), VIDEO_DAC_THS8134B (U1#3.6)
VGA_BLUE3: FPGA (U1#1.A10), VIDEO_DAC_THS8134B (U1#3.5)
VGA_BLUE4: FPGA (U1#1.B10), VIDEO_DAC_THS8134B (U1#3.4)
VGA_BLUE5: FPGA (U1#1.D10), VIDEO_DAC_THS8134B (U1#3.3)
VGA_BLUE6: FPGA (U1#1.G10), VIDEO_DAC_THS8134B (U1#3.2)
VGA_BLUE7: FPGA (U1#1.E10), VIDEO_DAC_THS8134B (U1#3.1)
VGA_GREEN0: FPGA (U1#1.D8), VIDEO_DAC_THS8134B (U1#3.34)
VGA_GREEN1: FPGA (U1#1.C8), VIDEO_DAC_THS8134B (U1#3.33)
VGA_GREEN2: FPGA (U1#1.F8), VIDEO_DAC_THS8134B (U1#3.32)
VGA_GREEN3: FPGA (U1#1.B7), VIDEO_DAC_THS8134B (U1#3.31)
VGA_GREEN4: FPGA (U1#1.E7), VIDEO_DAC_THS8134B (U1#3.30)
VGA_GREEN5: FPGA (U1#1.F7), VIDEO_DAC_THS8134B (U1#3.29)
VGA_GREEN6: FPGA (U1#1.D6), VIDEO_DAC_THS8134B (U1#3.28)
VGA_GREEN7: FPGA (U1#1.G8), VIDEO_DAC_THS8134B (U1#3.27)
VGA_RED0: FPGA (U1#1.A9), VIDEO_DAC_THS8134B (U1#3.15)
VGA_RED1: FPGA (U1#1.B9), VIDEO_DAC_THS8134B (U1#3.16)
VGA_RED2: FPGA (U1#1.D9), VIDEO_DAC_THS8134B (U1#3.17)
VGA_RED3: FPGA (U1#1.G9), VIDEO_DAC_THS8134B (U1#3.18)
VGA_RED4: FPGA (U1#1.A8), VIDEO_DAC_THS8134B (U1#3.19)
VGA_RED5: FPGA (U1#1.J9), VIDEO_DAC_THS8134B (U1#3.20)
VGA_RED6: FPGA (U1#1.H9), VIDEO_DAC_THS8134B (U1#3.21)
VGA_RED7: FPGA (U1#1.B8), VIDEO_DAC_THS8134B (U1#3.22)

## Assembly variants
Production: not fitted RN1 RN2 RN3 RN4 RN5 RN6 RN7 RN8 RN17 RN18 RN19 RN20 RN21 RN22 RN23 RN24 RN25 RN26 RN27 RN28 RN29 RN30 RN31 RN32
